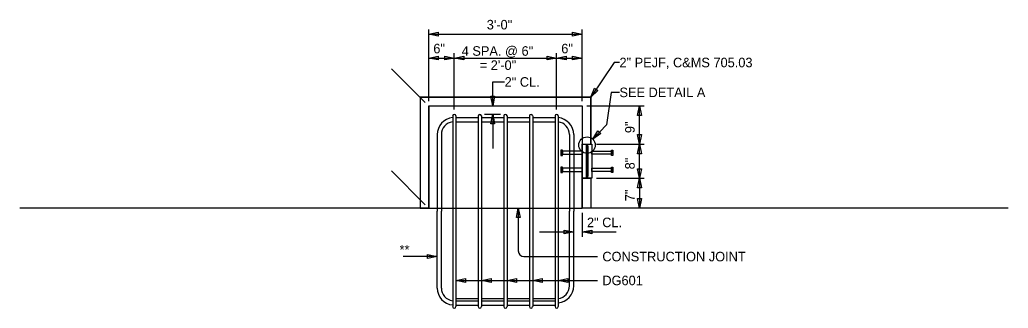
# Model space of a CAD drawing. Extents: x 1539537 to 1543620, y 586918 to 587460.
# Drawn here: x 1543043.59 to 1543058.08, y 587131.11 to 587135.34 of the extents above; entities that cross this region are included whole.
import ezdxf

# ---------------------------------------------------------------- set-up
doc = ezdxf.new("R2010")
doc.units = 0
doc.layers.add('SC_Scratch13', color=7, linetype='Continuous')

msp = doc.modelspace()

# ---------------------------------------------------------------- linework, layer by layer
at = {"layer": 'SC_Scratch13'}
for p, q in [((1543049.582, 587134.151), (1543049.582, 587135.201)), ((1543049.582, 587135.131), (1543051.832, 587135.131)), ((1543051.832, 587134.151), (1543051.832, 587135.201)), ((1543049.957, 587134.026), (1543049.957, 587134.851)), ((1543051.457, 587134.026), (1543051.457, 587134.851)), ((1543049.582, 587134.781), (1543049.957, 587134.781)), ((1543049.957, 587134.781), (1543051.457, 587134.781)), ((1543051.457, 587134.781), (1543051.832, 587134.781)), ((1543049.533, 587134.13), (1543049.038, 587134.625)), ((1543050.52, 587134.081), (1543050.52, 587134.431)), ((1543050.52, 587134.431), (1543050.695, 587134.431)), ((1543052.257, 587134.278), (1543052.187, 587133.801)), ((1543052.378, 587134.278), (1543052.257, 587134.278)), ((1543049.457, 587134.206), (1543049.457, 587132.581)), ((1543049.457, 587134.206), (1543051.957, 587134.206)), ((1543051.957, 587134.206), (1543051.957, 587133.518)), ((1543049.582, 587134.081), (1543051.832, 587134.081)), ((1543049.582, 587134.081), (1543049.582, 587132.581)), ((1543051.832, 587134.081), (1543051.832, 587132.581)), ((1543051.902, 587134.081), (1543052.741, 587134.081)), ((1543052.671, 587133.518), (1543052.671, 587134.081)), ((1543049.934, 587133.932), (1543049.934, 587131.136)), ((1543049.981, 587133.932), (1543049.981, 587131.136)), ((1543049.981, 587133.909), (1543050.309, 587133.909)), ((1543049.981, 587133.847), (1543050.309, 587133.847)), ((1543050.309, 587133.932), (1543050.309, 587131.136)), ((1543050.356, 587133.932), (1543050.356, 587131.136)), ((1543050.356, 587133.909), (1543050.684, 587133.909)), ((1543050.356, 587133.847), (1543050.684, 587133.847)), ((1543050.402, 587133.956), (1543050.637, 587133.956)), ((1543050.52, 587133.956), (1543050.52, 587133.456)), ((1543050.684, 587133.932), (1543050.684, 587131.136)), ((1543050.731, 587133.932), (1543050.731, 587131.136)), ((1543050.731, 587133.909), (1543051.059, 587133.909)), ((1543050.731, 587133.847), (1543051.059, 587133.847)), ((1543051.059, 587133.932), (1543051.059, 587131.136)), ((1543051.106, 587133.932), (1543051.106, 587131.136)), ((1543051.106, 587133.909), (1543051.434, 587133.909)), ((1543051.106, 587133.847), (1543051.434, 587133.847)), ((1543051.434, 587133.932), (1543051.434, 587131.136)), ((1543051.481, 587133.932), (1543051.481, 587131.136)), ((1543052.187, 587133.801), (1543051.987, 587133.592)), ((1543049.707, 587133.659), (1543049.707, 587132.534)), ((1543049.77, 587133.659), (1543049.77, 587132.534)), ((1543051.645, 587133.659), (1543051.645, 587132.534)), ((1543051.707, 587133.659), (1543051.707, 587132.534)), ((1543051.908, 587133.487), (1543051.908, 587133.518)), ((1543052.041, 587133.518), (1543052.741, 587133.518)), ((1543052.671, 587133.018), (1543052.671, 587133.518)), ((1543049.533, 587132.63), (1543049.038, 587133.125)), ((1543051.908, 587133.05), (1543051.908, 587133.018)), ((1543051.957, 587133.018), (1543051.957, 587132.581)), ((1543052.041, 587133.018), (1543052.741, 587133.018)), ((1543052.671, 587133.018), (1543052.671, 587132.581)), ((1543049.582, 587132.581), (1543043.59, 587132.581)), ((1543049.582, 587132.581), (1543051.832, 587132.581)), ((1543049.707, 587131.409), (1543049.707, 587132.534)), ((1543049.77, 587131.409), (1543049.77, 587132.534)), ((1543050.895, 587132.581), (1543050.895, 587131.953)), ((1543051.645, 587131.44), (1543051.645, 587132.534)), ((1543051.707, 587131.44), (1543051.707, 587132.534)), ((1543058.075, 587132.581), (1543051.832, 587132.581)), ((1543051.832, 587132.511), (1543051.832, 587132.161)), ((1543051.207, 587132.231), (1543051.707, 587132.231)), ((1543051.832, 587132.231), (1543052.332, 587132.231)), ((1543049.707, 587131.87), (1543049.207, 587131.87)), ((1543050.978, 587131.87), (1543052.057, 587131.87)), ((1543049.981, 587131.52), (1543052.057, 587131.52)), ((1543049.981, 587131.253), (1543050.309, 587131.253)), ((1543049.981, 587131.222), (1543050.309, 587131.222)), ((1543050.356, 587131.253), (1543050.684, 587131.253)), ((1543050.356, 587131.222), (1543050.684, 587131.222)), ((1543050.731, 587131.253), (1543051.059, 587131.253)), ((1543050.731, 587131.222), (1543051.059, 587131.222)), ((1543051.106, 587131.253), (1543051.434, 587131.253)), ((1543051.106, 587131.222), (1543051.434, 587131.222)), ((1543049.981, 587131.159), (1543050.309, 587131.159)), ((1543050.356, 587131.159), (1543050.684, 587131.159)), ((1543050.731, 587131.159), (1543051.059, 587131.159)), ((1543051.106, 587131.159), (1543051.434, 587131.159))]:
    msp.add_line(p, q, dxfattribs=at)
for points in [[(1543049.722, 587135.159), (1543049.722, 587135.103), (1543049.582, 587135.131)], [(1543051.692, 587135.103), (1543051.692, 587135.159), (1543051.832, 587135.131)], [(1543049.722, 587134.809), (1543049.722, 587134.753), (1543049.582, 587134.781)], [(1543049.817, 587134.753), (1543049.817, 587134.809), (1543049.957, 587134.781)], [(1543050.097, 587134.809), (1543050.097, 587134.753), (1543049.957, 587134.781)], [(1543051.317, 587134.753), (1543051.317, 587134.809), (1543051.457, 587134.781)], [(1543051.597, 587134.809), (1543051.597, 587134.753), (1543051.457, 587134.781)], [(1543051.692, 587134.753), (1543051.692, 587134.809), (1543051.832, 587134.781)], [(1543052.012, 587134.338), (1543052.059, 587134.307), (1543051.957, 587134.206)], [(1543049.457, 587132.581), (1543049.582, 587132.581), (1543049.582, 587134.081), (1543051.832, 587134.081), (1543051.832, 587133.518), (1543051.957, 587133.518), (1543051.957, 587134.206), (1543049.457, 587134.206)], [(1543050.492, 587134.221), (1543050.548, 587134.221), (1543050.52, 587134.081)], [(1543052.699, 587133.941), (1543052.643, 587133.941), (1543052.671, 587134.081)], [(1543050.548, 587133.816), (1543050.492, 587133.816), (1543050.52, 587133.956)], [(1543052.063, 587133.713), (1543052.104, 587133.674), (1543051.987, 587133.592)], [(1543052.643, 587133.658), (1543052.699, 587133.658), (1543052.671, 587133.518)], [(1543051.543, 587133.432), (1543051.52, 587133.432), (1543051.52, 587133.354), (1543051.543, 587133.354)], [(1543051.832, 587133.417), (1543051.543, 587133.417), (1543051.543, 587133.37), (1543051.832, 587133.37)], [(1543051.832, 587133.518), (1543051.895, 587133.518), (1543051.895, 587133.018), (1543051.832, 587133.018)], [(1543051.895, 587133.518), (1543051.908, 587133.518), (1543051.908, 587133.487), (1543051.901, 587133.487), (1543051.901, 587133.503), (1543051.895, 587133.503)], [(1543051.895, 587133.503), (1543051.901, 587133.503), (1543051.901, 587133.034), (1543051.895, 587133.034)], [(1543051.901, 587133.487), (1543051.916, 587133.487), (1543051.916, 587133.05), (1543051.901, 587133.05)], [(1543051.971, 587133.417), (1543052.26, 587133.417), (1543052.26, 587133.37), (1543051.971, 587133.37)], [(1543052.26, 587133.432), (1543052.283, 587133.432), (1543052.283, 587133.354), (1543052.26, 587133.354)], [(1543052.699, 587133.378), (1543052.643, 587133.378), (1543052.671, 587133.518)], [(1543051.543, 587133.182), (1543051.52, 587133.182), (1543051.52, 587133.104), (1543051.543, 587133.104)], [(1543051.832, 587133.167), (1543051.543, 587133.167), (1543051.543, 587133.12), (1543051.832, 587133.12)], [(1543051.971, 587133.167), (1543052.26, 587133.167), (1543052.26, 587133.12), (1543051.971, 587133.12)], [(1543052.26, 587133.182), (1543052.283, 587133.182), (1543052.283, 587133.104), (1543052.26, 587133.104)], [(1543052.643, 587133.158), (1543052.699, 587133.158), (1543052.671, 587133.018)], [(1543051.832, 587132.581), (1543051.832, 587133.018), (1543051.957, 587133.018), (1543051.957, 587132.581)], [(1543052.699, 587132.878), (1543052.643, 587132.878), (1543052.671, 587133.018)], [(1543052.643, 587132.721), (1543052.699, 587132.721), (1543052.671, 587132.581)], [(1543050.923, 587132.441), (1543050.867, 587132.441), (1543050.895, 587132.581)], [(1543051.567, 587132.203), (1543051.567, 587132.259), (1543051.707, 587132.231)], [(1543051.972, 587132.259), (1543051.972, 587132.203), (1543051.832, 587132.231)], [(1543049.567, 587131.842), (1543049.567, 587131.898), (1543049.707, 587131.87)], [(1543050.121, 587131.548), (1543050.121, 587131.492), (1543049.981, 587131.52)], [(1543050.496, 587131.548), (1543050.496, 587131.492), (1543050.356, 587131.52)], [(1543050.871, 587131.548), (1543050.871, 587131.492), (1543050.731, 587131.52)], [(1543051.246, 587131.548), (1543051.246, 587131.492), (1543051.106, 587131.52)], [(1543051.621, 587131.548), (1543051.621, 587131.492), (1543051.481, 587131.52)]]:
    msp.add_lwpolyline(points, close=True, dxfattribs=at)
for points in [[(1543052.378, 587134.716), (1543052.299, 587134.716), (1543051.957, 587134.206)], [(1543051.908, 587133.487), (1543051.908, 587133.518), (1543051.971, 587133.518), (1543051.971, 587133.018), (1543051.908, 587133.018), (1543051.908, 587133.05)]]:
    msp.add_lwpolyline(points, dxfattribs=at)
msp.add_circle((1543051.903, 587133.505), 0.121, dxfattribs=at)
for centre, radius, start, end in [((1543049.957, 587133.659), 0.25, 95.3794, 180), ((1543049.957, 587133.659), 0.188, 97.1808, 180), ((1543049.957, 587133.932), 0.0234, 0, 180), ((1543050.332, 587133.932), 0.0234, 0, 180), ((1543050.707, 587133.932), 0.0234, 0, 180), ((1543051.082, 587133.932), 0.0234, 0, 180), ((1543051.457, 587133.932), 0.0234, 0, 180), ((1543051.457, 587133.659), 0.25, 360, 84.6206), ((1543051.457, 587133.659), 0.188, 0, 82.8192), ((1543050.978, 587131.953), 0.0833, 180, 270), ((1543049.957, 587131.409), 0.25, 180, 264.6206), ((1543049.957, 587131.409), 0.188, 180, 262.8192), ((1543051.457, 587131.44), 0.188, 277.1808, 360), ((1543051.457, 587131.44), 0.25, 275.3794, 360), ((1543049.957, 587131.136), 0.0234, 180, 0), ((1543050.332, 587131.136), 0.0234, 180, 0), ((1543050.707, 587131.136), 0.0234, 180, 0), ((1543051.082, 587131.136), 0.0234, 180, 0), ((1543051.457, 587131.136), 0.0234, 180, 0)]:
    msp.add_arc(centre, radius, start, end, dxfattribs=at)

# ---------------------------------------------------------------- texts
for s, p in [('3\'-0"', (1543050.433, 587135.201)), ('6"', (1543049.65, 587134.851)), ('6"', (1543051.525, 587134.851)), ('4 SPA. @ 6"', (1543050.066, 587134.815)), ('= 2\'-0"', (1543050.33, 587134.607)), ('2" PEJF, C&MS 705.03', (1543052.378, 587134.646)), ('2" CL.', (1543050.695, 587134.361)), ('SEE DETAIL A', (1543052.378, 587134.208)), ('2" CL.', (1543051.902, 587132.301)), ('**', (1543049.156, 587131.902)), ('CONSTRUCTION JOINT', (1543052.127, 587131.8)), ('DG601', (1543052.127, 587131.45))]:
    msp.add_text(s, height=0.14, dxfattribs=at).set_placement(p)
for s, p in [('9"', (1543052.601, 587133.68)), ('8"', (1543052.601, 587133.149)), ('7"', (1543052.601, 587132.682))]:
    msp.add_text(s, height=0.14, rotation=90, dxfattribs=at).set_placement(p)

doc.saveas('drawing.dxf')
